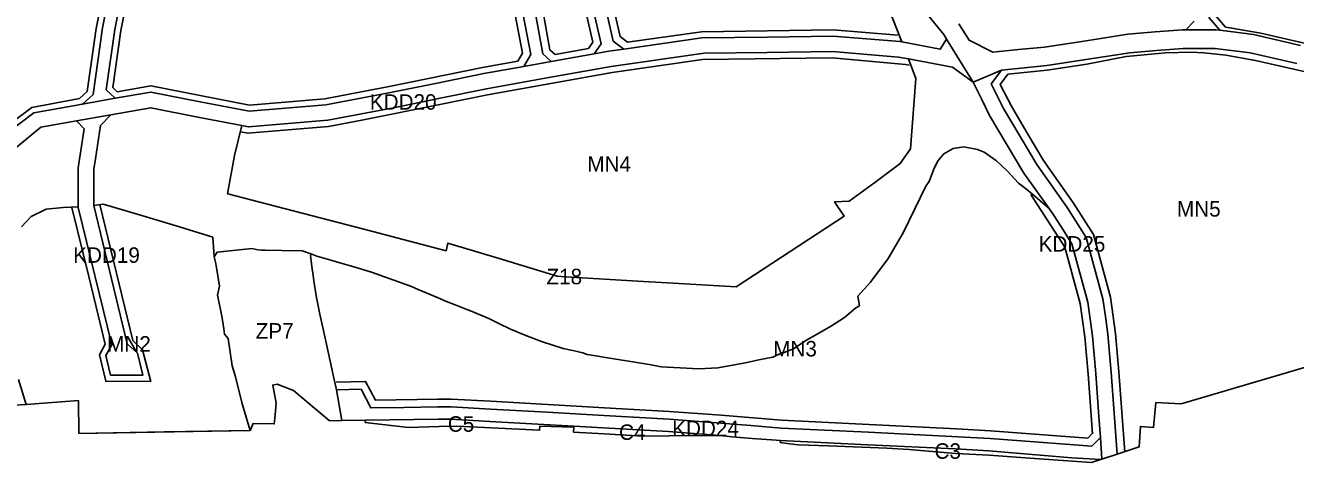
# Model space of a CAD drawing. Extents: x 7428841 to 7433518, y 5545054 to 5546840.
# Drawn here: x 7430662 to 7431482, y 5545180 to 5545462 of the extents above; entities that cross this region are included whole.
import ezdxf

# ---------------------------------------------------------------- set-up
doc = ezdxf.new("R2010")
doc.units = 0
for name, color, linetype in [('linie_rozgraniczajace', 7, 'Continuous'), ('linie_zabudowy_nieprzekraczalne', 7, 'Continuous'), ('oznaczenia_przeznaczen', 7, 'Continuous')]:
    doc.layers.add(name, color=color, linetype=linetype)

msp = doc.modelspace()

# ---------------------------------------------------------------- linework, layer by layer
at = {"layer": 'linie_rozgraniczajace'}
for points in [[(7431485.58, 5545449.26), (7431455.18, 5545456.33), (7431433.47, 5545459.03), (7431426.65, 5545467.02), (7431426.51, 5545475.32), (7431426.41, 5545483.29), (7431426.77, 5545495.25), (7431428.46, 5545516.04), (7431428.54, 5545534.6), (7431426.88, 5545536.71), (7431418.18, 5545554.23), (7431416.43, 5545563.75), (7431417.23, 5545582.58), (7431420.37, 5545591.94)], [(7430655.35, 5545522.49), (7430669.3, 5545524.96), (7430693.05, 5545526.75), (7430714.35, 5545527.61), (7430717.28, 5545527.72), (7430722.64, 5545522.01), (7430719.46, 5545500.94), (7430711.59, 5545460.59), (7430705.41, 5545417.58), (7430698.5, 5545411.3), (7430667.19, 5545405.74), (7430649.43, 5545392.37)], [(7431023.91, 5545493.16), (7431033.75, 5545450.33), (7431029.31, 5545443.81), (7431001.49, 5545438.87), (7430996.06, 5545443.73), (7430990.86, 5545472)], [(7431218.74, 5545475.08), (7431227.96, 5545451.48), (7431226.93, 5545451.68), (7431183.5, 5545455.23), (7431141.17, 5545454.64), (7431098.84, 5545454.06), (7431048.4, 5545446.86), (7431041.57, 5545452.05), (7431031.71, 5545494.92)], [(7430713.91, 5545420.49), (7430719.51, 5545459.45), (7430723.43, 5545479.52)], [(7431483.24, 5545437.48), (7431453.07, 5545444.5), (7431430.48, 5545447.31), (7431409.82, 5545447.33), (7431392.59, 5545445.93), (7431375.36, 5545444.52), (7431348.51, 5545440.37), (7431321.66, 5545436.22), (7431307.01, 5545434.78), (7431292.35, 5545433.35), (7431274.12, 5545425.46), (7431256.98, 5545453.19), (7431255.08, 5545456.28), (7431237.74, 5545477.67)], [(7430990.86, 5545472), (7430996.06, 5545443.73), (7431001.49, 5545438.87), (7430983.71, 5545435.71), (7430988.24, 5545443.3), (7430983.11, 5545470.03)], [(7430983.11, 5545470.03), (7430988.24, 5545443.3)], [(7431426.65, 5545467.02), (7431433.47, 5545459.03), (7431431.23, 5545459.31), (7431420.29, 5545459.32), (7431411.64, 5545459.33), (7431416.82, 5545464.92)], [(7431416.82, 5545464.92), (7431411.64, 5545459.33), (7431409.34, 5545459.33), (7431391.65, 5545457.89), (7431373.96, 5545456.45), (7431347.06, 5545452.29), (7431320.15, 5545448.13), (7431303.46, 5545446.49), (7431286.76, 5545444.85), (7431271.51, 5545452.52), (7431264.89, 5545463.23)], [(7431264.89, 5545463.23), (7431271.51, 5545452.52), (7431286.76, 5545444.85), (7431303.46, 5545446.49), (7431320.15, 5545448.13), (7431347.06, 5545452.29), (7431373.96, 5545456.45), (7431391.65, 5545457.89), (7431409.34, 5545459.33), (7431411.64, 5545459.33), (7431420.29, 5545459.32), (7431431.23, 5545459.31), (7431433.47, 5545459.03), (7431455.18, 5545456.33), (7431485.58, 5545449.26)], [(7430649.43, 5545392.37), (7430667.19, 5545405.74), (7430698.5, 5545411.3), (7430719.79, 5545415.07), (7430742.75, 5545419.13), (7430774.54, 5545412.91), (7430806.32, 5545406.7), (7430855.72, 5545410.84), (7430897.51, 5545418.75), (7430927.7, 5545424.94), (7430957.89, 5545431.13), (7430983.71, 5545435.71), (7431001.49, 5545438.87), (7431029.31, 5545443.81), (7431038.71, 5545445.48), (7431048.4, 5545446.86), (7431098.84, 5545454.06), (7431141.17, 5545454.64), (7431183.5, 5545455.23), (7431226.93, 5545451.68), (7431227.96, 5545451.48), (7431252.82, 5545446.74), (7431256.98, 5545453.19), (7431274.12, 5545425.46), (7431260.72, 5545435.28), (7431232.23, 5545440.56), (7431225.87, 5545441.74), (7431183.16, 5545445.23), (7431141.07, 5545444.64), (7431100.25, 5545444.16), (7431040.29, 5545435.6), (7430999.97, 5545428.44), (7430959.64, 5545421.28), (7430929.67, 5545415.14), (7430899.45, 5545408.94), (7430857.08, 5545400.91), (7430805.77, 5545396.62), (7430801.52, 5545397.44), (7430774.21, 5545402.79), (7430742.66, 5545408.96), (7430716.87, 5545404.4), (7430694.75, 5545400.48), (7430671.62, 5545396.42), (7430655.46, 5545383.04)], [(7430988.24, 5545443.3), (7430983.71, 5545435.71), (7430957.89, 5545431.13), (7430927.7, 5545424.94), (7430897.51, 5545418.75), (7430855.72, 5545410.84), (7430806.32, 5545406.7), (7430774.54, 5545412.91), (7430742.75, 5545419.13), (7430719.79, 5545415.07), (7430713.91, 5545420.49)], [(7431490.36, 5545241.93), (7431408.52, 5545217.78), (7431392.17, 5545218.63), (7431390.7, 5545202.64), (7431382.17, 5545203.21), (7431381.38, 5545190.05), (7431367.12, 5545185.37), (7431365.2, 5545211.76), (7431363.28, 5545238.15), (7431361.19, 5545262.76), (7431359.56, 5545274.18), (7431357.94, 5545285.6), (7431352.56, 5545305.39), (7431347.18, 5545325.18), (7431334.84, 5545344.68), (7431315.28, 5545372.28), (7431293.71, 5545408.48), (7431285.7, 5545424.5), (7431292.35, 5545433.35), (7431307.01, 5545434.78), (7431321.66, 5545436.22), (7431348.51, 5545440.37), (7431375.36, 5545444.52), (7431392.59, 5545445.93), (7431409.82, 5545447.33), (7431430.48, 5545447.31), (7431453.07, 5545444.5), (7431483.24, 5545437.48)], [(7430705.86, 5545345.87), (7430705.84, 5545357.6), (7430705.81, 5545369.34), (7430706.96, 5545375.9), (7430710.12, 5545397.5), (7430716.87, 5545404.4), (7430742.66, 5545408.96), (7430774.21, 5545402.79), (7430801.52, 5545397.44), (7430796.74, 5545378.09), (7430792.37, 5545353.39), (7430792.41, 5545353.38), (7430807.36, 5545349.53), (7430886.15, 5545329.04), (7430909.88, 5545322.84), (7430933.62, 5545316.63), (7430934.58, 5545321.65), (7430969.94, 5545310.94), (7431005.29, 5545300.23), (7431007.86, 5545300.02), (7431017.76, 5545299.43), (7431064.79, 5545296.63), (7431069.14, 5545296.37), (7431121.06, 5545293.27), (7431155.87, 5545316.19), (7431190.72, 5545338.92), (7431184.62, 5545348.2), (7431194.07, 5545348.58), (7431210.53, 5545360.74), (7431227, 5545372.91), (7431233.73, 5545382.49), (7431237.08, 5545427.97), (7431232.23, 5545440.56), (7431260.72, 5545435.28), (7431274.12, 5545425.46), (7431279.45, 5545414.73), (7431284.77, 5545404.01), (7431306.89, 5545366.82), (7431323.16, 5545343.88), (7431318.98, 5545347.6), (7431314.05, 5545352), (7431308.78, 5545356.2), (7431303.5, 5545360.4), (7431296.13, 5545368.2), (7431289.14, 5545374.77), (7431281.27, 5545380.33), (7431276.95, 5545381.95), (7431268.02, 5545383.69), (7431261.16, 5545382.59), (7431255.06, 5545379.22), (7431251.43, 5545374.86), (7431248.99, 5545370.05), (7431245.71, 5545361.28), (7431243.55, 5545358.36), (7431236.51, 5545343.78), (7431228.94, 5545328.25), (7431219.16, 5545311.56), (7431207.69, 5545296.31), (7431199.52, 5545287.39), (7431200.57, 5545281.11), (7431198.35, 5545279.89), (7431190.89, 5545273.67), (7431182.55, 5545268.3), (7431174.29, 5545263.48), (7431166.04, 5545258.67), (7431157.92, 5545253.43), (7431151.91, 5545251.04), (7431150.46, 5545250.69), (7431144.56, 5545248), (7431135.62, 5545246.19), (7431127.03, 5545244.31), (7431109.21, 5545241.09), (7431096.78, 5545240.42), (7431084.77, 5545241.03), (7431072.45, 5545241.75), (7431065.95, 5545243.01), (7431054.13, 5545245), (7431037.84, 5545247.62), (7431029.01, 5545249.06), (7431024.79, 5545249.72), (7431021.8, 5545250.87), (7431015.51, 5545252.18), (7431009.21, 5545253.49), (7430995.23, 5545258.01), (7430985.15, 5545262.04), (7430975.06, 5545266.07), (7430968.08, 5545269.52), (7430961.09, 5545272.97), (7430953.43, 5545276.21), (7430950.35, 5545277.52), (7430944.85, 5545279.62), (7430939.36, 5545281.72), (7430933.85, 5545284.01), (7430928.33, 5545286.31), (7430915.51, 5545291.67), (7430911.08, 5545293.51), (7430885.26, 5545302.81), (7430874, 5545306.35), (7430866.48, 5545308.42), (7430858.96, 5545310.5)], [(7430655.46, 5545383.04), (7430671.62, 5545396.42), (7430694.75, 5545400.48), (7430699.68, 5545395.36), (7430695.81, 5545370.09), (7430695.86, 5545345.03), (7430686.15, 5545344.56), (7430675.14, 5545343.54), (7430665.45, 5545338.74), (7430659.25, 5545332.04)], [(7430659.25, 5545332.04), (7430665.45, 5545338.74), (7430675.14, 5545343.54), (7430686.15, 5545344.56), (7430695.86, 5545345.03), (7430695.86, 5545344.66), (7430717.47, 5545255.94), (7430713.72, 5545249.07), (7430716.76, 5545236.42), (7430737.52, 5545236.33), (7430734.08, 5545250.53), (7430727.53, 5545256.53), (7430705.86, 5545345.87), (7430712, 5545346.71), (7430725.9, 5545342.69), (7430739.79, 5545338.67), (7430761.25, 5545332.01), (7430782.71, 5545325.36), (7430783.67, 5545312.82), (7430784.46, 5545309.34), (7430785.25, 5545305.85), (7430787.05, 5545293.87), (7430785.83, 5545287.94), (7430786.92, 5545282.78), (7430788, 5545277.61), (7430788.98, 5545271.91), (7430789.96, 5545266.21), (7430790.38, 5545262.92), (7430792.64, 5545260.08), (7430795.4, 5545242.31), (7430797.31, 5545236.2), (7430801.59, 5545218.78), (7430804.38, 5545209.18), (7430806.86, 5545200.69), (7430696.31, 5545198.78), (7430696.06, 5545219.92), (7430662.16, 5545217.46), (7430657.25, 5545233.5)], [(7430858.96, 5545310.5), (7430854.49, 5545311.86), (7430850.01, 5545313.22), (7430846.72, 5545314.4), (7430840.51, 5545316.64), (7430827.35, 5545316.89), (7430816.6, 5545316.95), (7430814.19, 5545317.14), (7430811.78, 5545317.32), (7430807.95, 5545318.15), (7430785.58, 5545315.74), (7430783.67, 5545312.82), (7430782.71, 5545325.36), (7430761.25, 5545332.01), (7430739.79, 5545338.67), (7430725.9, 5545342.69), (7430712, 5545346.71), (7430705.86, 5545345.87)], [(7430657.25, 5545233.5), (7430662.16, 5545217.46), (7430651.46, 5545216.69)]]:
    msp.add_lwpolyline(points, dxfattribs=at)
for points in [[(7431002.55, 5545562.92), (7431012.92, 5545566.24), (7431015.88, 5545567.2), (7431015.94, 5545567), (7431020.07, 5545553.65), (7431018.27, 5545549.15), (7431021.86, 5545537.79), (7431031.71, 5545494.92), (7431041.57, 5545452.05), (7431048.4, 5545446.86), (7431038.71, 5545445.48), (7431029.31, 5545443.81), (7431033.75, 5545450.33), (7431023.91, 5545493.16), (7431014.06, 5545536), (7431010.49, 5545547.22), (7431006.69, 5545549.52)], [(7430698.5, 5545411.3), (7430705.41, 5545417.58), (7430711.59, 5545460.59), (7430719.46, 5545500.94), (7430722.64, 5545522.01), (7430717.28, 5545527.72), (7430731.66, 5545528.25), (7430737.53, 5545528.46), (7430730.79, 5545522.39), (7430730.41, 5545522.08), (7430730.14, 5545519.97), (7430728.86, 5545510.07), (7430727.76, 5545501.48), (7430727.34, 5545499.58), (7430723.43, 5545479.52), (7430719.51, 5545459.45), (7430713.91, 5545420.49), (7430719.79, 5545415.07)], [(7431209.11, 5545499.74), (7431211.72, 5545499.85), (7431222.4, 5545490.74), (7431237.74, 5545477.67), (7431255.08, 5545456.28), (7431256.98, 5545453.19), (7431252.82, 5545446.74), (7431227.96, 5545451.48), (7431218.74, 5545475.08)], [(7430792.37, 5545353.39), (7430796.74, 5545378.09), (7430801.52, 5545397.44), (7430805.77, 5545396.62), (7430857.08, 5545400.91), (7430899.45, 5545408.94), (7430929.67, 5545415.14), (7430959.64, 5545421.28), (7430999.97, 5545428.44), (7431040.29, 5545435.6), (7431100.25, 5545444.16), (7431141.07, 5545444.64), (7431183.16, 5545445.23), (7431225.87, 5545441.74), (7431232.23, 5545440.56), (7431237.08, 5545427.97), (7431233.73, 5545382.49), (7431227, 5545372.91), (7431210.53, 5545360.74), (7431194.07, 5545348.58), (7431184.62, 5545348.2), (7431190.72, 5545338.92), (7431155.87, 5545316.19), (7431121.06, 5545293.27), (7431069.14, 5545296.37), (7431064.79, 5545296.63), (7431017.76, 5545299.43), (7431007.86, 5545300.02), (7431005.29, 5545300.23), (7430969.94, 5545310.94), (7430934.58, 5545321.65), (7430933.62, 5545316.63), (7430909.88, 5545322.84), (7430886.15, 5545329.04), (7430807.36, 5545349.53), (7430792.41, 5545353.38)], [(7431274.12, 5545425.46), (7431292.35, 5545433.35), (7431285.7, 5545424.5), (7431293.71, 5545408.48), (7431315.28, 5545372.28), (7431334.84, 5545344.68), (7431347.18, 5545325.18), (7431352.56, 5545305.39), (7431357.94, 5545285.6), (7431359.56, 5545274.18), (7431361.19, 5545262.76), (7431363.28, 5545238.15), (7431365.2, 5545211.76), (7431367.12, 5545185.37), (7431357.33, 5545182.16), (7431356.32, 5545196.19), (7431355.32, 5545209.75), (7431353.32, 5545237.36), (7431352.28, 5545249.5), (7431351.25, 5545261.63), (7431348.13, 5545283.57), (7431337.93, 5545321.1), (7431332.23, 5545330.11), (7431326.53, 5545339.11), (7431323.16, 5545343.88), (7431306.89, 5545366.82), (7431284.77, 5545404.01), (7431279.45, 5545414.73)], [(7430695.86, 5545344.66), (7430695.86, 5545345.03), (7430695.81, 5545370.09), (7430699.68, 5545395.36), (7430694.75, 5545400.48), (7430716.87, 5545404.4), (7430710.12, 5545397.5), (7430706.96, 5545375.9), (7430705.81, 5545369.34), (7430705.84, 5545357.6), (7430705.86, 5545345.87), (7430727.53, 5545256.53), (7430734.08, 5545250.53), (7430737.52, 5545236.33), (7430716.76, 5545236.42), (7430713.72, 5545249.07), (7430717.47, 5545255.94)], [(7430845.94, 5545313.57), (7430846.72, 5545314.4), (7430850.01, 5545313.22), (7430854.49, 5545311.86), (7430858.96, 5545310.5), (7430866.48, 5545308.42), (7430874, 5545306.35), (7430885.26, 5545302.81), (7430911.08, 5545293.51), (7430915.51, 5545291.67), (7430928.33, 5545286.31), (7430933.85, 5545284.01), (7430939.36, 5545281.72), (7430944.85, 5545279.62), (7430950.35, 5545277.52), (7430953.43, 5545276.21), (7430961.09, 5545272.97), (7430968.08, 5545269.52), (7430975.06, 5545266.07), (7430985.15, 5545262.04), (7430995.23, 5545258.01), (7431009.21, 5545253.49), (7431015.51, 5545252.18), (7431021.8, 5545250.87), (7431024.79, 5545249.72), (7431029.01, 5545249.06), (7431037.84, 5545247.62), (7431054.13, 5545245), (7431065.95, 5545243.01), (7431072.45, 5545241.75), (7431084.77, 5545241.03), (7431096.78, 5545240.42), (7431109.21, 5545241.09), (7431127.03, 5545244.31), (7431135.62, 5545246.19), (7431144.56, 5545248), (7431150.46, 5545250.69), (7431151.91, 5545251.04), (7431157.92, 5545253.43), (7431166.04, 5545258.67), (7431174.29, 5545263.48), (7431182.55, 5545268.3), (7431190.89, 5545273.67), (7431198.35, 5545279.89), (7431200.57, 5545281.11), (7431199.52, 5545287.39), (7431207.69, 5545296.31), (7431219.16, 5545311.56), (7431228.94, 5545328.25), (7431236.51, 5545343.78), (7431243.55, 5545358.36), (7431245.71, 5545361.28), (7431248.99, 5545370.05), (7431251.43, 5545374.86), (7431255.06, 5545379.22), (7431261.16, 5545382.59), (7431268.02, 5545383.69), (7431276.95, 5545381.95), (7431281.27, 5545380.33), (7431289.14, 5545374.77), (7431296.13, 5545368.2), (7431303.5, 5545360.4), (7431308.78, 5545356.2), (7431314.05, 5545352), (7431318.98, 5545347.6), (7431323.16, 5545343.88), (7431326.53, 5545339.11), (7431332.23, 5545330.11), (7431337.93, 5545321.1), (7431348.13, 5545283.57), (7431351.25, 5545261.63), (7431352.28, 5545249.5), (7431353.32, 5545237.36), (7431355.32, 5545209.75), (7431356.32, 5545196.19), (7431350.78, 5545190.44), (7431285.07, 5545195.47), (7431206.56, 5545199.46), (7431150.04, 5545202.23), (7431130.51, 5545203.84), (7431077.68, 5545207.93), (7431035.57, 5545210.33), (7430998.9, 5545212.42), (7430962.23, 5545214.5), (7430936.81, 5545215.95), (7430928.27, 5545215.84), (7430906.55, 5545215.54), (7430884.83, 5545215.24), (7430878.57, 5545227.28), (7430862.74, 5545226.88), (7430860.26, 5545237.47), (7430855.73, 5545258.33), (7430852.02, 5545275.66), (7430849.61, 5545287.5), (7430848.1, 5545297.15), (7430847.55, 5545300.73), (7430846.82, 5545306.6), (7430846.38, 5545310.08)], [(7430783.67, 5545312.82), (7430785.58, 5545315.74), (7430807.95, 5545318.15), (7430811.78, 5545317.32), (7430814.19, 5545317.14), (7430816.6, 5545316.95), (7430827.35, 5545316.89), (7430840.51, 5545316.64), (7430846.72, 5545314.4), (7430845.94, 5545313.57), (7430846.38, 5545310.08), (7430846.82, 5545306.6), (7430847.55, 5545300.73), (7430848.1, 5545297.15), (7430849.61, 5545287.5), (7430852.02, 5545275.66), (7430855.73, 5545258.33), (7430860.26, 5545237.47), (7430862.74, 5545226.88), (7430866.2, 5545207.02), (7430860.51, 5545206.94), (7430858.05, 5545207.04), (7430835.01, 5545226.44), (7430824.45, 5545230.51), (7430821.55, 5545229.97), (7430823.69, 5545218.28), (7430822.78, 5545208.44), (7430822.45, 5545204.88), (7430808.83, 5545205.15), (7430806.86, 5545200.69), (7430804.38, 5545209.18), (7430801.59, 5545218.78), (7430797.31, 5545236.2), (7430795.4, 5545242.31), (7430792.64, 5545260.08), (7430790.38, 5545262.92), (7430789.96, 5545266.21), (7430788.98, 5545271.91), (7430788, 5545277.61), (7430786.92, 5545282.78), (7430785.83, 5545287.94), (7430787.05, 5545293.87), (7430785.25, 5545305.85), (7430784.46, 5545309.34)], [(7430862.74, 5545226.88), (7430878.57, 5545227.28), (7430884.83, 5545215.24), (7430906.55, 5545215.54), (7430928.27, 5545215.84), (7430936.81, 5545215.95), (7430962.23, 5545214.5), (7430998.9, 5545212.42), (7431035.57, 5545210.33), (7431077.68, 5545207.93), (7431130.51, 5545203.84), (7431150.04, 5545202.23), (7431206.56, 5545199.46), (7431285.07, 5545195.47), (7431350.78, 5545190.44), (7431356.32, 5545196.19), (7431357.33, 5545182.16), (7431356.39, 5545181.85), (7431337.84, 5545182.89), (7431284.19, 5545187.5), (7431262.67, 5545188.7), (7431206.09, 5545191.47), (7431149.52, 5545194.24), (7431146.76, 5545194.42), (7431131.35, 5545195.54), (7431118.32, 5545196.53), (7431110.35, 5545197.48), (7431077.15, 5545199.95), (7431035.11, 5545202.35), (7431016.04, 5545203.43), (7431016.01, 5545203.43), (7430961.78, 5545206.52), (7430936.63, 5545207.95), (7430928.38, 5545207.84), (7430881.35, 5545207.22), (7430866.2, 5545207.02)], [(7430881.28, 5545205.78), (7430881.35, 5545207.22), (7430928.38, 5545207.84), (7430936.63, 5545207.95), (7430961.78, 5545206.52), (7431016.01, 5545203.43), (7431016.04, 5545203.43), (7431016.1, 5545202.84), (7430994.08, 5545203.36), (7430993.95, 5545200.78), (7430940.55, 5545203.45), (7430929.1, 5545203.12), (7430909.26, 5545202.54)], [(7431015.93, 5545199.59), (7431016.1, 5545202.84), (7431016.04, 5545203.43), (7431035.11, 5545202.35), (7431077.15, 5545199.95), (7431110.35, 5545197.48), (7431077.52, 5545197.12), (7431060.97, 5545196.95), (7431035.62, 5545198.44)], [(7431149.44, 5545192.82), (7431149.52, 5545194.24), (7431206.09, 5545191.47), (7431262.67, 5545188.7), (7431284.19, 5545187.5), (7431337.84, 5545182.89), (7431356.39, 5545181.85), (7431350.51, 5545179.92), (7431338.29, 5545180.82), (7431310.73, 5545182.85), (7431284.4, 5545184.69), (7431262.93, 5545185.71), (7431232.78, 5545188.29), (7431218.31, 5545189.31), (7431180.74, 5545190.79), (7431161.19, 5545191.42), (7431155.74, 5545192.07)]]:
    msp.add_lwpolyline(points, close=True, dxfattribs=at)
at = {"layer": 'linie_zabudowy_nieprzekraczalne'}
for points in [[(7431467.97, 5545698.58), (7431453.46, 5545626.4), (7431444.32, 5545617.55), (7431435.24, 5545607.58), (7431427.57, 5545596.9), (7431424.05, 5545590.35), (7431421.2, 5545581.85), (7431420.45, 5545564.03), (7431422.01, 5545555.5), (7431430.27, 5545538.86), (7431432.56, 5545535.96), (7431432.41, 5545523.87), (7431432.46, 5545515.89), (7431430.76, 5545495.03), (7431430.41, 5545483.26), (7431430.63, 5545468.52), (7431437.1, 5545460.94)], [(7431025.61, 5545447.22), (7431028.39, 5545451.34), (7431009.24, 5545534.68), (7431006.3, 5545543.91), (7431002.48, 5545546.22), (7430996.31, 5545566.17), (7431019.27, 5545573.53), (7431025.83, 5545553.18), (7431023.58, 5545548.95), (7431026.69, 5545539.1), (7431046.03, 5545454.93), (7431050.82, 5545451.3)], [(7430979.9, 5545439.11), (7430982.97, 5545444.23), (7430978.21, 5545469), (7430969.95, 5545504.78), (7430963.45, 5545523.09), (7430960.21, 5545524.85), (7430918.32, 5545510.33), (7430915.04, 5545502.53), (7430894.19, 5545497.77), (7430889.94, 5545519.73), (7430972.23, 5545550.76), (7430987.68, 5545506.87), (7430995.76, 5545472.98), (7431000.67, 5545446.32), (7431003.99, 5545443.38)], [(7430696.65, 5545415.04), (7430701.65, 5545419.57), (7430707.41, 5545460.11), (7430715.52, 5545501.63), (7430718.39, 5545520.69), (7430713.74, 5545525.55)], [(7430741.21, 5545526.39), (7430734.53, 5545520.37), (7430731.28, 5545498.9), (7430723.45, 5545458.79), (7430718.16, 5545422.01), (7430720.92, 5545419.33)], [(7431050.82, 5545451.3), (7431098.53, 5545458.05), (7431183.64, 5545459.23), (7431225.35, 5545455.82)], [(7431437.1, 5545460.94), (7431439.95, 5545460.67), (7431460.09, 5545457.1), (7431506.73, 5545446.48), (7431533.09, 5545441.2), (7431546.9, 5545448.68)], [(7431003.99, 5545443.38), (7431025.61, 5545447.22)], [(7431537.38, 5545412.87), (7431531.04, 5545423.28), (7431512.6, 5545426.83), (7431456.52, 5545439.45), (7431437.32, 5545442.86), (7431423.17, 5545444.54), (7431415.26, 5545444.9), (7431398.17, 5545444.33), (7431384.65, 5545443.12), (7431373.07, 5545442.05), (7431347.57, 5545437.08), (7431322.03, 5545433.25), (7431296.58, 5545430.64)], [(7430720.92, 5545419.33), (7430742.78, 5545423.19), (7430806.54, 5545410.73), (7430855.18, 5545414.8), (7430896.74, 5545422.67), (7430957.14, 5545435.06), (7430979.9, 5545439.11)], [(7431232.66, 5545436.41), (7431230.42, 5545436.83), (7431183.01, 5545441.22), (7431099.29, 5545440.06), (7431040.93, 5545431.65), (7430960.39, 5545417.36), (7430930.47, 5545411.22), (7430879.02, 5545401), (7430857.62, 5545396.95), (7430805.53, 5545392.58), (7430800.98, 5545393.51), (7430800.8, 5545393.55)], [(7431296.58, 5545430.64), (7431291.59, 5545424.01), (7431298.89, 5545409.94), (7431308.8, 5545392.92), (7431319.47, 5545375.01), (7431339, 5545347.47), (7431351.81, 5545327.21), (7431362.85, 5545286.61), (7431366.16, 5545263.32), (7431368.27, 5545238.54), (7431372.04, 5545186.7)], [(7430665.82, 5545409.14), (7430696.65, 5545415.04)], [(7430584.46, 5545312.01), (7430586.43, 5545312.41), (7430596.99, 5545319.05), (7430646.28, 5545394.58), (7430665.82, 5545409.14)], [(7431351.13, 5545198.47), (7431348.33, 5545236.97), (7431346.28, 5545261.07), (7431343.22, 5545282.56), (7431333.31, 5545319.04), (7431311.4, 5545352.89)], [(7430709.84, 5545346.42), (7430731.1, 5545258.8), (7430737.4, 5545252.69), (7430742.69, 5545232.3), (7430713.59, 5545232.44), (7430709.59, 5545249.39), (7430713.22, 5545256.27), (7430702.62, 5545299.99), (7430691.78, 5545344.51)], [(7431371.02, 5545186.65), (7431381.38, 5545190.05), (7431382.17, 5545203.21), (7431390.7, 5545202.64), (7431392.17, 5545218.63), (7431408.52, 5545217.78), (7431449.44, 5545229.86), (7431469.9, 5545235.89), (7431490.36, 5545241.93)], [(7430862.61, 5545231.87), (7430881.56, 5545232.36), (7430887.84, 5545220.28), (7430928.21, 5545220.84), (7430936.92, 5545220.95), (7430962.51, 5545219.5), (7431035.85, 5545215.33), (7431078, 5545212.92), (7431111.36, 5545210.44), (7431150.37, 5545207.22), (7431263.34, 5545201.68), (7431285.4, 5545200.45), (7431348.13, 5545195.65), (7431351.4, 5545199.22)], [(7430662.16, 5545217.46), (7430696.06, 5545219.92), (7430696.31, 5545198.78), (7430751.58, 5545199.73), (7430806.86, 5545200.69)]]:
    msp.add_lwpolyline(points, dxfattribs=at)

# ---------------------------------------------------------------- texts
at = {"layer": 'oznaczenia_przeznaczen'}
for s, p in [('KDD20', (7430884.24, 5545407.74)), ('MN4', (7431024.8, 5545367.71)), ('MN5', (7431405.83, 5545338.7)), ('KDD25', (7431316.43, 5545316.1)), ('KDD19', (7430692.55, 5545308.86)), ('Z18', (7430998.39, 5545295.02)), ('ZP7', (7430810.5, 5545259.93)), ('MN2', (7430714.5, 5545251.53)), ('MN3', (7431144.89, 5545248.43)), ('C5', (7430934.65, 5545199.81)), ('C4', (7431045.29, 5545194.57)), ('KDD24', (7431079.62, 5545196.94)), ('C3', (7431249.15, 5545182.37))]:
    msp.add_text(s, height=10, dxfattribs=at).set_placement(p)

doc.saveas('drawing.dxf')
